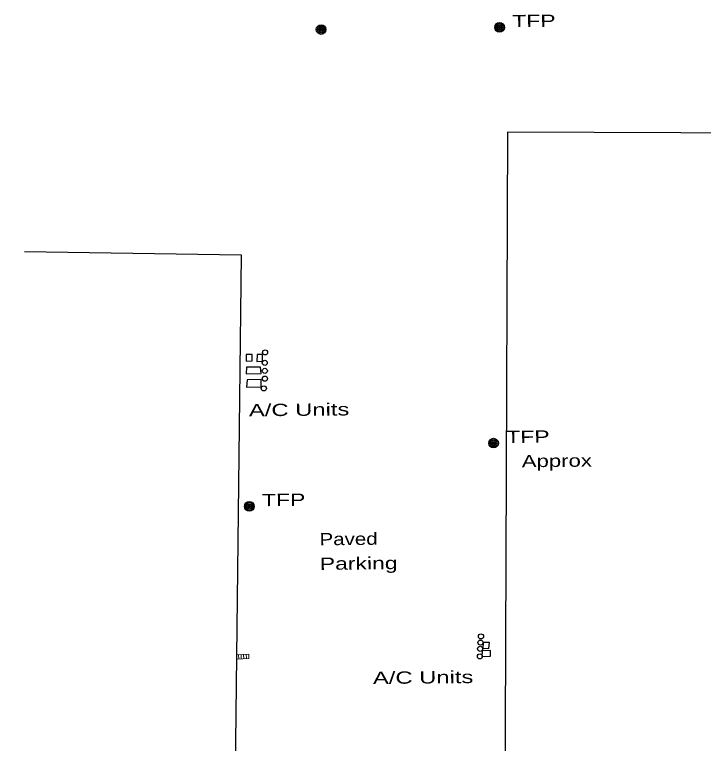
# Model space of a CAD drawing. Extents: x 2362213 to 2366494, y 6968794 to 6978110.
# Drawn here: x 2363855.3 to 2364125, y 6974966.6 to 6975251.8 of the extents above; entities that cross this region are included whole.
import ezdxf

# ---------------------------------------------------------------- set-up
doc = ezdxf.new("R2010")
doc.units = 0
doc.header["$LTSCALE"] = 1.9
for name, color, linetype, lineweight in [('11', 7, 'Continuous', 25), ('16', 7, 'Continuous', 13), ('2', 7, 'Continuous', 25), ('20', 7, 'Continuous', 25), ('23', 7, 'Continuous', 25)]:
    doc.layers.add(name, color=color, linetype=linetype, lineweight=lineweight)

msp = doc.modelspace()

# ---------------------------------------------------------------- linework, layer by layer
at = {"layer": '11'}
msp.add_lwpolyline([(2364144.499, 6974705.543), (2364144.65, 6974735.807), (2364151.03, 6974735.778), (2364151.301, 6974795.572), (2364145.771, 6974795.6), (2364145.92, 6974826.173), (2364151.409, 6974826.146), (2364152.012, 6974945.557), (2364147.142, 6974945.58), (2364147.239, 6974965.852), (2364153.059, 6974965.828), (2364153.569, 6975085.578), (2364148.939, 6975085.594), (2364149.041, 6975115.776), (2364154.952, 6975115.753), (2364155.191, 6975175.679), (2364150.001, 6975175.699), (2364150.119, 6975205.342), (2364048.33, 6975205.742), (2364046.369, 6974705.929)], close=True, dxfattribs=at)
msp.add_lwpolyline([(2363859.195, 6975159.148), (2363944.003, 6975157.727), (2363938.825, 6974708.955), (2363855.325, 6974709.56)], dxfattribs=at)
at = {"layer": '16'}
for p, q in [((2363946.98, 6975001.537), (2363942.201, 6975001.321)), ((2363942.201, 6975001.321), (2363942.277, 6974999.582)), ((2363947.057, 6974999.798), (2363942.277, 6974999.582)), ((2363942.981, 6975001.359), (2363943.057, 6974999.62)), ((2363943.981, 6975001.408), (2363944.058, 6974999.669)), ((2363944.981, 6975001.448), (2363945.057, 6974999.709)), ((2363945.98, 6975001.497), (2363946.057, 6974999.758)), ((2363946.98, 6975001.537), (2363947.057, 6974999.798))]:
    msp.add_line(p, q, dxfattribs=at)
at = {"layer": '20'}
for centre, radius in [((2363975.334, 6975245.949), 1.9), ((2363975.334, 6975245.949), 1.442), ((2364045.179, 6975246.804), 1.9), ((2364045.179, 6975246.804), 1.442), ((2364045.179, 6975246.804), 0.973), ((2364045.179, 6975246.804), 0.539), ((2364045.179, 6975246.804), 0.192), ((2363975.334, 6975245.949), 0.973), ((2363975.334, 6975245.949), 0.539), ((2363975.334, 6975245.949), 0.192), ((2364042.838, 6975084.104), 1.9), ((2364042.838, 6975084.104), 1.442), ((2364042.838, 6975084.104), 0.973), ((2364042.838, 6975084.104), 0.539), ((2364042.838, 6975084.104), 0.192), ((2363947.209, 6975059.372), 1.9), ((2363947.209, 6975059.372), 1.442), ((2363947.209, 6975059.372), 0.973), ((2363947.209, 6975059.372), 0.539), ((2363947.209, 6975059.372), 0.192)]:
    msp.add_circle(centre, radius, dxfattribs=at)
at = {"layer": '23'}
for points in [[(2363948.284, 6975118.785), (2363946.024, 6975118.763), (2363945.949, 6975116.122), (2363948.277, 6975116.315)], [(2363952.433, 6975118.834), (2363950.273, 6975118.854), (2363950.159, 6975116.102), (2363952.359, 6975116.153)], [(2363951.611, 6975113.826), (2363946.14, 6975113.864), (2363945.995, 6975111.284), (2363951.915, 6975111.33)], [(2363951.927, 6975108.999), (2363946.328, 6975108.816), (2363946.185, 6975106.064), (2363951.864, 6975106.138)], [(2364041.24, 6975006.155), (2364038.73, 6975006.131), (2364038.642, 6975003.83), (2364040.983, 6975003.812)], [(2364041.64, 6975002.998), (2364038.441, 6975002.878), (2364038.243, 6975000.606), (2364041.581, 6975000.808)]]:
    msp.add_lwpolyline(points, close=True, dxfattribs=at)
for centre in [(2363953.406, 6975119.604), (2363953.245, 6975115.522), (2363953.294, 6975112.392), (2363953.343, 6975109.333), (2363952.89, 6975105.518), (2364037.918, 6975008.473), (2364037.574, 6975003.62), (2364037.721, 6975006.061), (2364037.512, 6975000.659)]:
    msp.add_circle(centre, 1, dxfattribs=at)

# ---------------------------------------------------------------- texts
at = {"layer": '2'}
for s, width, p in [('Paved', 1.25, (2363974.736, 6975044.113)), ('Parking', 1.4, (2363974.827, 6975034.514))]:
    msp.add_text(s, height=4.8, rotation=0.546, dxfattribs=dict(at, width=width)).set_placement(p)
at = {"layer": '20'}
for s, width, p in [('  TFP', 1.4, (2364045.179, 6975246.804)), ('  TFP', 1.4, (2364042.838, 6975084.104)), ('Approx', 1.35, (2364053.907, 6975074.669)), ('  TFP', 1.4, (2363947.209, 6975059.372))]:
    msp.add_text(s, height=4.8, rotation=0.546, dxfattribs=dict(at, width=width)).set_placement(p)
at = {"layer": '23', "width": 1.45}
for p in [(2363947.094, 6975094.592), (2363995.643, 6974989.86)]:
    msp.add_text('A/C Units', height=4.8, rotation=0.546, dxfattribs=at).set_placement(p)

doc.saveas('drawing.dxf')
